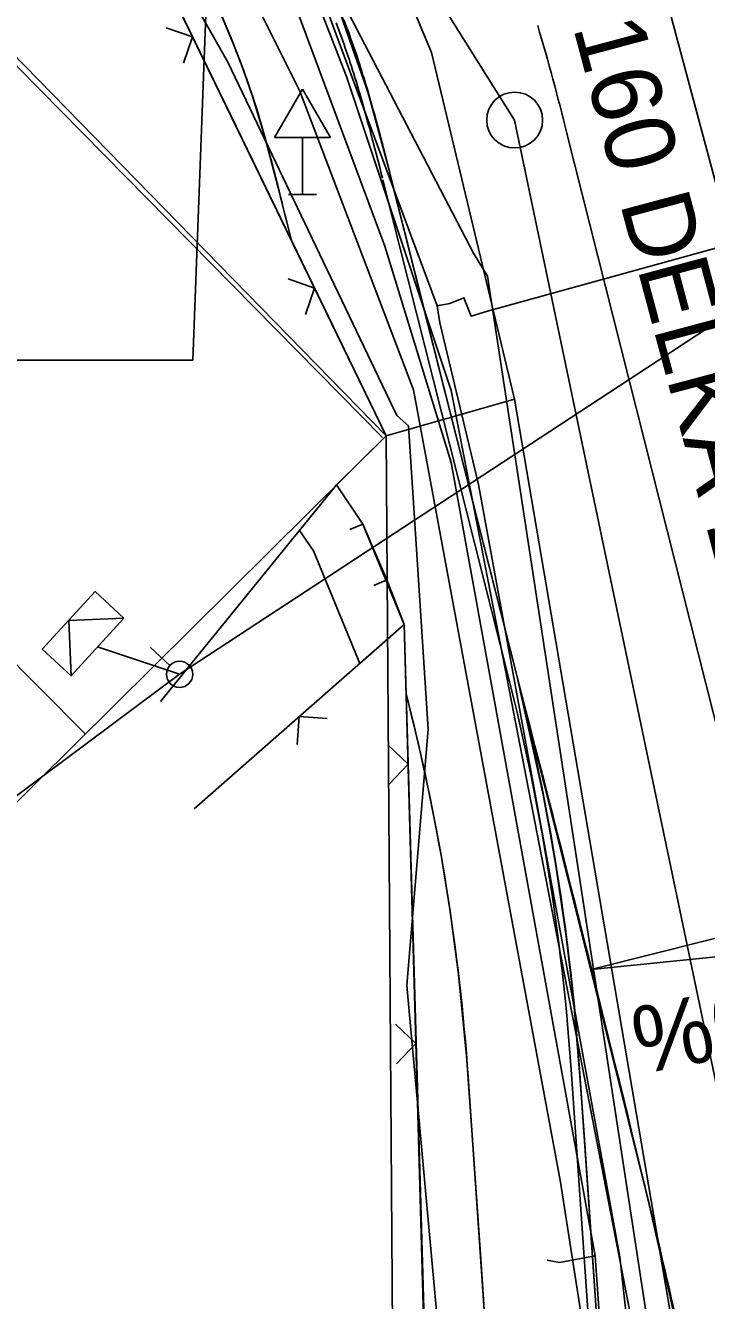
# Model space of a CAD drawing. Extents: x -643342 to -638635, y -1201752 to -1189948.
# Drawn here: x -639523.25 to -639511.06, y -1192633.18 to -1192610.36 of the extents above; entities that cross this region are included whole.
import ezdxf

# ---------------------------------------------------------------- set-up
doc = ezdxf.new("R2010")
doc.units = 0
for name, color, linetype in [('42', 7, 'Continuous'), ('IS_EL_NN_NADZEMNÍ', 7, 'Continuous'), ('IS_EL_NN_PODZEMNÍ', 7, 'Continuous'), ('IS_PLYN_STL', 7, 'Continuous'), ('IS_TELEF_MISTNI_ZAMERENO', 7, 'Continuous'), ('IS_VODOVOD_PRIPOJKA HYDRANT', 7, 'Continuous'), ('IS_VODOVOD_VAS', 7, 'Continuous'), ('IS_VODOVOD_ZRUSENY', 7, 'Continuous'), ('K-HRANICE_KN', 7, 'Continuous'), ('N-CHODNIK', 7, 'Continuous'), ('N-KAN_DEST_SACHTY-NÁVRH', 7, 'Continuous'), ('N-KAN_DEST_TRASA-NÁVRH', 7, 'Continuous'), ('N-OBVOD STAVBY 06', 7, 'Continuous'), ('N-OSA', 7, 'Continuous'), ('N-SILNICE', 7, 'Continuous'), ('N-SO101_KLOPENI', 7, 'Continuous'), ('N-SRAFY_PLOCHY', 7, 'Continuous'), ('N-SVAHOVÁNÍ', 7, 'Continuous'), ('tomaštík - Džuganovi - Vrstva 36', 7, 'Continuous'), ('Z-budovy', 7, 'Continuous'), ('Z-hrany_a_čáry', 7, 'Continuous'), ('Z-vchody_vjezdy', 7, 'Continuous'), ('Z-značky', 7, 'Continuous')]:
    doc.layers.add(name, color=color, linetype=linetype)

msp = doc.modelspace()

# ---------------------------------------------------------------- linework, layer by layer
at = {"layer": '42'}
for p, q in [((-639513.245, -1192604.369), (-639506.814, -1192628.443)), ((-639520.256, -1192616.346), (-639519.963, -1192608.704)), ((-639520.256, -1192616.346), (-639573.902, -1192616.346))]:
    msp.add_line(p, q, dxfattribs=at)
at = {"layer": 'IS_EL_NN_NADZEMNÍ'}
for points in [[(-639521.487, -1192620.965), (-639522.476, -1192621.006), (-639522.434, -1192621.995)], [(-639520.663, -1192621.811), (-639521.01, -1192621.493)]]:
    msp.add_lwpolyline(points, dxfattribs=at)
msp.add_circle((-639520.491, -1192621.97), 0.235, dxfattribs=at)
at = {"layer": 'IS_EL_NN_PODZEMNÍ'}
for p, q in [((-639505.76, -1192612.31), (-639520.49, -1192621.97)), ((-639520.49, -1192621.97), (-639521.96, -1192621.48)), ((-639520.49, -1192621.97), (-639537.94, -1192634.94))]:
    msp.add_line(p, q, dxfattribs=at)
msp.add_lwpolyline([(-639521.487, -1192620.965), (-639522.434, -1192621.995), (-639522.95, -1192621.521), (-639522.002, -1192620.49)], close=True, dxfattribs=at)
at = {"layer": 'IS_PLYN_STL'}
msp.add_lwpolyline([(-639519.8, -1192608.6), (-639518.34, -1192611.53), (-639516.3, -1192616.88), (-639515.62, -1192620.55), (-639513.67, -1192631.06), (-639513.06, -1192634.97), (-639512.85, -1192638.89), (-639512.56, -1192644.42), (-639512.26, -1192649.59)], dxfattribs=at)
at = {"layer": 'IS_TELEF_MISTNI_ZAMERENO'}
for p, q in [((-639521.25, -1192608.13), (-639519.63, -1192611.01)), ((-639519.63, -1192611.01), (-639516.6, -1192617.34)), ((-639516.6, -1192617.34), (-639516.39, -1192617.52)), ((-639516.39, -1192617.52), (-639516.04, -1192622.95)), ((-639516.04, -1192622.95), (-639516.42, -1192627.54)), ((-639516.42, -1192627.54), (-639515.7, -1192635.44))]:
    msp.add_line(p, q, dxfattribs=at)
at = {"layer": 'IS_VODOVOD_PRIPOJKA HYDRANT'}
msp.add_lwpolyline([(-639513.05, -1192632.38), (-639513.69, -1192632.5), (-639513.91, -1192632.46)], dxfattribs=at)
at = {"layer": 'IS_VODOVOD_VAS'}
for points in [[(-639574.178, -1192545), (-639565.32, -1192554.2), (-639544.196, -1192576.345), (-639543.991, -1192576.56), (-639543.73, -1192576.83), (-639534.504, -1192586.506), (-639531.24, -1192590.494), (-639527.133, -1192595.51), (-639522.796, -1192601.597), (-639522.77, -1192601.637), (-639518.91, -1192607.22), (-639515.881, -1192615.376)], [(-639574.504, -1192545.287), (-639565.62, -1192554.6), (-639534.876, -1192586.834), (-639527.527, -1192595.81), (-639523.229, -1192601.871), (-639519.29, -1192607.54), (-639519.07, -1192608.24), (-639516.818, -1192614.307), (-639515.63, -1192618.18), (-639513.05, -1192632.38), (-639511.6, -1192653.11)], [(-639514.98, -1192615.47), (-639510.115, -1192614.124), (-639507.62, -1192612.39), (-639505.99, -1192609.86), (-639482.51, -1192597.47), (-639478.03, -1192595.29)], [(-639515.65, -1192615.33), (-639515.4, -1192615.23), (-639515.27, -1192615.56), (-639514.98, -1192615.47)], [(-639515.881, -1192615.376), (-639515.65, -1192615.33)], [(-639515.881, -1192615.376), (-639515.83, -1192615.68)], [(-639515.83, -1192615.68), (-639515.14, -1192618.57), (-639512.61, -1192632.4), (-639512.36, -1192634.62), (-639510.88, -1192653.55), (-639509.514, -1192661.694), (-639508.846, -1192665.91), (-639508.251, -1192671.127), (-639508.199, -1192671.584), (-639508.152, -1192671.995), (-639508.128, -1192672.212), (-639507.893, -1192674.271), (-639506.803, -1192678.209), (-639504.641, -1192690.968), (-639504.581, -1192691.325), (-639503.907, -1192695.302)]]:
    msp.add_lwpolyline(points, dxfattribs=at)
at = {"layer": 'IS_VODOVOD_ZRUSENY'}
for points in [[(-639573.944, -1192546.368), (-639550.08, -1192573.56), (-639545.32, -1192575.03), (-639544.04, -1192576.59), (-639530.53, -1192590.38), (-639522.03, -1192601.36), (-639515.23, -1192614.43)], [(-639515.23, -1192614.43), (-639514.98, -1192614.84), (-639507.86, -1192661.34), (-639506.03, -1192670.84), (-639505.88, -1192671.62), (-639500.98, -1192698.45), (-639496.78, -1192729.96)]]:
    msp.add_lwpolyline(points, dxfattribs=at)
at = {"layer": 'K-HRANICE_KN'}
for p, q in [((-639537.98, -1192596.29), (-639516.86, -1192617.73)), ((-639543.41, -1192601.63), (-639522.19, -1192623.03)), ((-639515.979, -1192610.836), (-639518.131, -1192605.698)), ((-639515.979, -1192610.836), (-639518.131, -1192605.698)), ((-639516.79, -1192617.7), (-639521.35, -1192608.31)), ((-639514.492, -1192617.042), (-639515.979, -1192610.836)), ((-639514.492, -1192617.042), (-639515.979, -1192610.836)), ((-639516.79, -1192617.7), (-639514.492, -1192617.042)), ((-639516.79, -1192617.7), (-639514.492, -1192617.042)), ((-639500.054, -1192701.689), (-639514.492, -1192617.042)), ((-639500.054, -1192701.689), (-639514.492, -1192617.042)), ((-639516.79, -1192617.7), (-639545.828, -1192646.466)), ((-639516.79, -1192617.7), (-639545.828, -1192646.466)), ((-639516.534, -1192654.939), (-639516.79, -1192617.7)), ((-639516.534, -1192654.939), (-639516.79, -1192617.7))]:
    msp.add_line(p, q, dxfattribs=at)
at = {"layer": 'N-CHODNIK'}
for p, q in [((-639518.657, -1192613.53), (-639518.647, -1192613.573)), ((-639518.486, -1192614.207), (-639518.647, -1192613.573)), ((-639516.394, -1192622.482), (-639516.436, -1192622.316)), ((-639515.325, -1192629.174), (-639514.116, -1192646.65))]:
    msp.add_line(p, q, dxfattribs=at)
for points in [[(-639518.486, -1192614.207), (-639516.79, -1192617.7), (-639517.68, -1192618.58)], [(-639517.68, -1192618.58), (-639517.21, -1192619.28), (-639516.78, -1192620.28), (-639516.47, -1192621.08), (-639516.436, -1192622.316)]]:
    msp.add_lwpolyline(points, dxfattribs=at)
for centre, radius, start, end in [((-639551.769, -1192623.654), 34.75, 21.3416, 24.2064), ((-639533.2, -1192616.221), 14.75, 17.0534, 20.8665), ((-639552.416, -1192621.768), 34.75, 13.7135, 16.5783), ((-639553.234, -1192631.798), 38, 3.9585, 14.191)]:
    msp.add_arc(centre, radius, start, end, dxfattribs=at)
at = {"layer": 'N-KAN_DEST_SACHTY-NÁVRH'}
msp.add_circle((-639514.491, -1192612.048), 0.5, dxfattribs=at)
at = {"layer": 'N-KAN_DEST_TRASA-NÁVRH'}
msp.add_lwpolyline([(-639583.962, -1192528.01), (-639550.452, -1192564.184), (-639529.583, -1192588.026), (-639514.491, -1192612.048), (-639507.737, -1192644.326), (-639498.832, -1192694.254), (-639511.439, -1192713.331), (-639516.613, -1192716.507), (-639553.938, -1192703.739), (-639570.485, -1192701.616), (-639578.687, -1192703.18)], dxfattribs=at)
at = {"layer": 'N-OBVOD STAVBY 06'}
msp.add_lwpolyline([(-639515.5, -1192654.75), (-639516.47, -1192621.08), (-639517.265, -1192621.777), (-639518.094, -1192619.759), (-639518.344, -1192619.397), (-639517.68, -1192618.58), (-639516.79, -1192617.7), (-639516.79, -1192617.7), (-639518.486, -1192614.207), (-639519.776, -1192611.551), (-639521.35, -1192608.31), (-639522.01, -1192607.61), (-639525.532, -1192604.05), (-639525.532, -1192604.05), (-639531.387, -1192595.182)], dxfattribs=at)
at = {"layer": 'N-OSA'}
msp.add_lwpolyline([(-639509.962, -1192626.503), (-639513.557, -1192612.286)], dxfattribs=at)
msp.add_arc((-639552.416, -1192621.768), 40, 13.7135, 16.5783, dxfattribs=at)
at = {"layer": 'N-SILNICE'}
for p, q in [((-639514.6, -1192622.028), (-639516.853, -1192613.119)), ((-639514.455, -1192621.992), (-639516.708, -1192613.082)), ((-639513.479, -1192629.047), (-639512.27, -1192646.522)), ((-639513.33, -1192629.036), (-639512.12, -1192646.512))]:
    msp.add_line(p, q, dxfattribs=at)
for centre, radius, start, end in [((-639533.2, -1192616.221), 16.75, 17.0534, 20.8665), ((-639533.2, -1192616.221), 16.6, 17.0534, 20.8665), ((-639552.416, -1192621.768), 36.6, 13.7135, 16.5783), ((-639552.416, -1192621.768), 36.75, 13.7135, 16.5783), ((-639553.234, -1192631.798), 39.85, 3.9585, 14.191), ((-639553.234, -1192631.798), 40, 3.9585, 14.191), ((-640053.348, -1192762.129), 556.817, 13.50356, 14.57672), ((-639654.778, -1192665.701), 146.75, 11.4488, 13.23615)]:
    msp.add_arc(centre, radius, start, end, dxfattribs=at)
at = {"layer": 'N-SO101_KLOPENI'}
msp.add_lwpolyline([(-639506.827, -1192625.671), (-639513.123, -1192627.255), (-639506.598, -1192626.593), (-639506.827, -1192625.671)], close=True, dxfattribs=at)
at = {"layer": 'N-SRAFY_PLOCHY'}
for p, q in [((-639517.332, -1192610.856), (-639517.803, -1192609.622)), ((-639517.755, -1192609.738), (-639517.112, -1192611.563)), ((-639519.875, -1192609.856), (-639519.57, -1192610.585)), ((-639519.57, -1192610.585), (-639519.371, -1192611.089)), ((-639517.048, -1192611.787), (-639517.332, -1192610.856)), ((-639519.371, -1192611.089), (-639519.198, -1192611.584)), ((-639519.198, -1192611.584), (-639519.012, -1192612.194)), ((-639517.112, -1192611.563), (-639516.757, -1192612.881)), ((-639516.818, -1192612.641), (-639517.048, -1192611.787)), ((-639519.012, -1192612.194), (-639518.905, -1192612.574)), ((-639518.905, -1192612.574), (-639518.723, -1192613.264)), ((-639515.928, -1192616.165), (-639516.818, -1192612.641)), ((-639516.757, -1192612.881), (-639516.264, -1192614.836)), ((-639518.723, -1192613.264), (-639518.486, -1192614.207)), ((-639518.486, -1192614.207), (-639516.79, -1192617.7)), ((-639516.264, -1192614.836), (-639515.735, -1192616.929)), ((-639515.233, -1192618.914), (-639515.928, -1192616.165)), ((-639515.735, -1192616.929), (-639515.336, -1192618.505)), ((-639516.79, -1192617.7), (-639517.68, -1192618.58)), ((-639515.336, -1192618.505), (-639514.4, -1192622.207)), ((-639517.68, -1192618.58), (-639517.21, -1192619.28)), ((-639514.455, -1192621.992), (-639515.233, -1192618.914)), ((-639517.21, -1192619.28), (-639516.47, -1192621.08)), ((-639516.47, -1192621.08), (-639516.436, -1192622.316)), ((-639513.951, -1192624.261), (-639514.455, -1192621.992)), ((-639513.371, -1192626.229), (-639514.455, -1192621.992)), ((-639514.455, -1192621.992), (-639514.014, -1192623.94)), ((-639516.436, -1192622.316), (-639516.22, -1192623.2)), ((-639516.394, -1192622.482), (-639516.436, -1192622.316)), ((-639514.4, -1192622.207), (-639513.304, -1192626.544)), ((-639516.22, -1192623.2), (-639516.006, -1192624.179)), ((-639514.014, -1192623.94), (-639513.768, -1192625.284)), ((-639516.006, -1192624.179), (-639515.816, -1192625.172)), ((-639513.745, -1192625.426), (-639513.951, -1192624.261)), ((-639515.816, -1192625.172), (-639515.647, -1192626.212)), ((-639513.768, -1192625.284), (-639513.583, -1192626.529)), ((-639513.566, -1192626.657), (-639513.745, -1192625.426)), ((-639515.647, -1192626.212), (-639515.496, -1192627.347)), ((-639513.083, -1192627.376), (-639513.371, -1192626.229)), ((-639513.583, -1192626.529), (-639513.436, -1192627.787)), ((-639513.437, -1192627.777), (-639513.566, -1192626.657)), ((-639513.304, -1192626.544), (-639512.093, -1192631.406)), ((-639515.496, -1192627.347), (-639515.352, -1192628.803)), ((-639512.809, -1192628.481), (-639513.083, -1192627.376)), ((-639513.339, -1192628.899), (-639513.437, -1192627.777)), ((-639513.436, -1192627.787), (-639513.321, -1192629.166)), ((-639512.309, -1192630.519), (-639512.809, -1192628.481)), ((-639515.352, -1192628.803), (-639515.252, -1192630.219)), ((-639513.248, -1192630.217), (-639513.339, -1192628.899)), ((-639514.116, -1192646.65), (-639515.325, -1192629.174)), ((-639513.321, -1192629.166), (-639513.289, -1192629.63)), ((-639513.289, -1192629.63), (-639513.187, -1192631.101)), ((-639515.252, -1192630.219), (-639515.105, -1192632.349)), ((-639513.158, -1192631.51), (-639513.248, -1192630.217)), ((-639511.925, -1192632.109), (-639512.309, -1192630.519)), ((-639513.187, -1192631.101), (-639513.085, -1192632.576)), ((-639512.205, -1192645.281), (-639513.158, -1192631.51)), ((-639512.093, -1192631.406), (-639511.143, -1192635.627)), ((-639511.571, -1192633.649), (-639511.925, -1192632.109)), ((-639515.105, -1192632.349), (-639514.885, -1192635.53)), ((-639513.085, -1192632.576), (-639513, -1192633.793))]:
    msp.add_line(p, q, dxfattribs=at)
for points in [[(-639522.01, -1192607.61), (-639521.35, -1192608.31), (-639518.486, -1192614.207), (-639518.647, -1192613.573), (-639518.657, -1192613.53)], [(-639516.436, -1192622.316), (-639515.5, -1192654.75), (-639513.004, -1192654.325)]]:
    msp.add_lwpolyline(points, dxfattribs=at)
for centre, radius, start, end in [((-639551.769, -1192623.654), 34.75, 21.379, 24.2064), ((-639533.2, -1192616.221), 14.75, 17.1345, 20.7854), ((-639552.416, -1192621.768), 34.75, 13.7135, 16.5409), ((-639553.234, -1192631.798), 38, 3.9585, 14.191)]:
    msp.add_arc(centre, radius, start, end, dxfattribs=at)
at = {"layer": 'N-SVAHOVÁNÍ'}
for points in [[(-639522.01, -1192607.61), (-639521.35, -1192608.31), (-639518.486, -1192614.207)], [(-639513.004, -1192654.325), (-639515.5, -1192654.75), (-639516.434, -1192622.323)]]:
    msp.add_lwpolyline(points, dxfattribs=at)
at = {"layer": 'Z-budovy'}
for p, q in [((-639532.275, -1192601.863), (-639516.79, -1192617.7)), ((-639516.79, -1192617.7), (-639517.68, -1192618.58)), ((-639517.68, -1192618.58), (-639520.834, -1192622.46))]:
    msp.add_line(p, q, dxfattribs=at)
at = {"layer": 'Z-hrany_a_čáry'}
for p, q in [((-639519.2, -1192606.9), (-639517.5, -1192611.27)), ((-639521.35, -1192608.31), (-639516.79, -1192617.7)), ((-639520.258, -1192610.559), (-639520.731, -1192610.395)), ((-639520.258, -1192610.559), (-639520.422, -1192611.032)), ((-639517.5, -1192611.27), (-639515.63, -1192616.89)), ((-639518.074, -1192615.057), (-639518.547, -1192614.893)), ((-639518.074, -1192615.057), (-639518.238, -1192615.53)), ((-639515.63, -1192616.89), (-639512.39, -1192633.56)), ((-639517.21, -1192619.28), (-639517.68, -1192618.58)), ((-639516.47, -1192621.08), (-639516.78, -1192620.28)), ((-639520.23, -1192624.376), (-639516.47, -1192621.08)), ((-639516.47, -1192621.08), (-639515.63, -1192651.27)), ((-639518.35, -1192622.728), (-639518.383, -1192623.228)), ((-639518.35, -1192622.728), (-639517.85, -1192622.761)), ((-639516.4, -1192623.579), (-639516.764, -1192623.235)), ((-639516.4, -1192623.579), (-639516.744, -1192623.943)), ((-639516.261, -1192628.577), (-639516.625, -1192628.233)), ((-639516.261, -1192628.577), (-639516.605, -1192628.941))]:
    msp.add_line(p, q, dxfattribs=at)
at = {"layer": 'Z-vchody_vjezdy'}
for p, q in [((-639517.44, -1192619.379), (-639517.21, -1192619.28)), ((-639516.78, -1192620.28), (-639517.21, -1192619.28)), ((-639517.01, -1192620.379), (-639516.78, -1192620.28))]:
    msp.add_line(p, q, dxfattribs=at)
at = {"layer": 'Z-značky'}
for p, q in [((-639518.29, -1192611.496), (-639518.79, -1192612.362)), ((-639517.79, -1192612.362), (-639518.29, -1192611.496)), ((-639518.79, -1192612.362), (-639517.79, -1192612.362)), ((-639518.29, -1192612.362), (-639518.29, -1192613.38)), ((-639518.54, -1192613.38), (-639518.04, -1192613.38))]:
    msp.add_line(p, q, dxfattribs=at)

# ---------------------------------------------------------------- texts
at = {"layer": 'N-SO101_KLOPENI'}
msp.add_text('5.0%', height=1.2, rotation=190.8409, dxfattribs=at).set_placement((-639508.881, -1192627.268))
at = {"layer": 'tomaštík - Džuganovi - Vrstva 36'}
for s, p in [('OCHRANNÁ TRUBKA ', (-639511.73, -1192607.132)), ('PE 160 DÉLKA 11,0 m', (-639514.146, -1192607.777))]:
    msp.add_text(s, height=1.25, rotation=284.9494, dxfattribs=at).set_placement(p)

doc.saveas('drawing.dxf')
